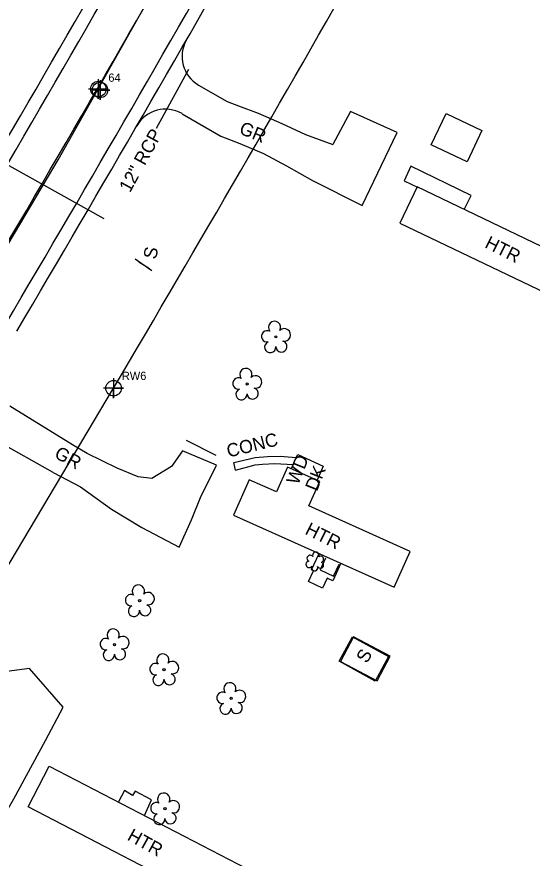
# Model space of a CAD drawing. Extents: x 1653123 to 1656194, y 596584 to 600233.
# Drawn here: x 1654045 to 1654201, y 598328.6 to 598583.3 of the extents above; entities that cross this region are included whole.
import ezdxf

# ---------------------------------------------------------------- set-up
doc = ezdxf.new("R2010")
doc.units = 0
for name, color, linetype in [('Default Symbol CELL', 7, 'Continuous'), ('Default Symbol Cogo Number', 7, 'Continuous'), ('Exist Building Text', 7, 'Continuous'), ('Exist Horizontal Alignment', 7, 'Continuous'), ('Exist Other Culture Area Outline Text', 7, 'Continuous'), ('Exist Other Culture Sign CELL', 7, 'Continuous'), ('Exist Other Culture Sign Text', 7, 'Continuous'), ('Exist Right of Way Line', 7, 'Continuous'), ('Exist Roads EOT', 7, 'Continuous'), ('Exist Roads Soil Text', 7, 'Continuous'), ('Exist Structure Minor Pipes RCP 12 Inch', 7, 'Continuous'), ('Exist Structure Minor Pipes RCP 12 Inch Text', 7, 'Continuous'), ('Exist Structure Minor Pipes RCP 18 Inch', 7, 'Continuous'), ('Exist Vegetation Tree CELL', 7, 'Continuous'), ('Old_Level_20', 7, 'Continuous'), ('Prop Conc Shoulder Berm Gutter', 7, 'Continuous'), ('Prop Easement Construction', 7, 'Continuous'), ('Prop Easement Permanent Drainage Station Offsets', 7, 'Continuous'), ('Prop ROW Station Offsets', 7, 'Continuous'), ('Prop Superelevation Label', 7, 'Continuous'), ('Scratch_Level_5', 7, 'Continuous')]:
    doc.layers.add(name, color=color, linetype=linetype)

msp = doc.modelspace()

# ---------------------------------------------------------------- linework, layer by layer
at = {"layer": 'Default Symbol CELL'}
for points in [[(1654069.68, 598564.47), (1654069.68, 598558.47), (1654069.68, 598561.47), (1654072.68, 598561.47), (1654066.68, 598561.47)], [(1654070.2, 598564.17), (1654070.2, 598558.17), (1654070.2, 598561.17), (1654073.2, 598561.17), (1654067.2, 598561.17)], [(1654074.29, 598473.91), (1654074.29, 598467.91), (1654074.29, 598470.91), (1654077.29, 598470.91), (1654071.29, 598470.91)]]:
    msp.add_lwpolyline(points, dxfattribs=at)
for centre in [(1654069.68, 598561.47), (1654070.2, 598561.17), (1654074.29, 598470.91)]:
    msp.add_circle(centre, 2.34, dxfattribs=at)
at = {"layer": 'Exist Horizontal Alignment'}
msp.add_arc((1646280.41, 603070.7), 9000, 329.451735, 330.4149, dxfattribs=at)
at = {"layer": 'Exist Other Culture Sign CELL'}
msp.add_line((1654080.82, 598510.08), (1654085.9, 598506.51), dxfattribs=at)
msp.add_lwpolyline([(1654081.92, 598509.18), (1654085.19, 598507.14)], dxfattribs=at)
at = {"layer": 'Exist Right of Way Line'}
msp.add_line((1654023, 598384.74), (1654074.29, 598470.91), dxfattribs=at)
for radius in [8950, 9050]:
    msp.add_arc((1646280.41, 603070.7), radius, 329.451735, 330.4149, dxfattribs=at)
at = {"layer": 'Exist Roads EOT'}
for radius in [8988, 9012]:
    msp.add_arc((1646280.41, 603070.7), radius, 329.451735, 330.4149, dxfattribs=at)
at = {"layer": 'Exist Structure Minor Pipes RCP 12 Inch'}
msp.add_lwpolyline([(1654087.24, 598549.61), (1654097.07, 598567.54)], dxfattribs=at)
at = {"layer": 'Exist Structure Minor Pipes RCP 18 Inch'}
msp.add_line((1654029.13, 598545.84), (1654071.38, 598522.3), dxfattribs=at)
at = {"layer": 'Exist Vegetation Tree CELL'}
for p, q in [((1654123.42, 598486.46), (1654123.42, 598486.46)), ((1654114.72, 598472.19), (1654114.72, 598472.19)), ((1654082.19, 598406.62), (1654082.19, 598406.62)), ((1654074.56, 598393.29), (1654074.56, 598393.29)), ((1654089.58, 598385.73), (1654089.58, 598385.73)), ((1654109.88, 598377.02), (1654109.88, 598377.02)), ((1654089.86, 598343.62), (1654089.86, 598343.62))]:
    msp.add_line(p, q, dxfattribs=at)
for centre in [(1654123.42, 598486.46), (1654114.72, 598472.19), (1654082.19, 598406.62), (1654074.56, 598393.29), (1654089.58, 598385.73), (1654109.88, 598377.02), (1654089.86, 598343.62)]:
    msp.add_circle(centre, 0.326, dxfattribs=at)
for centre, radius, start, end in [((1654123.03, 598489.33), 1.86, 330.1651, 219.7134), ((1654120.81, 598486.61), 1.73, 62.6636, 279.3457), ((1654125.97, 598487.05), 1.9, 257.1011, 134.1999), ((1654121.71, 598483.34), 1.69, 111.5671, 6.231), ((1654125.09, 598483.56), 1.7, 181.2822, 74.56), ((1654114.34, 598475.07), 1.86, 330.1651, 219.7134), ((1654117.27, 598472.78), 1.9, 257.1011, 134.1999), ((1654112.12, 598472.35), 1.73, 62.6636, 279.3457), ((1654113.02, 598469.07), 1.69, 111.5671, 6.231), ((1654116.4, 598469.29), 1.7, 181.2822, 74.56), ((1654081.8, 598409.49), 1.86, 330.1651, 219.7134), ((1654079.58, 598406.77), 1.73, 62.6636, 279.3457), ((1654084.74, 598407.2), 1.9, 257.1011, 134.1999), ((1654080.48, 598403.49), 1.69, 111.5671, 6.231), ((1654083.86, 598403.72), 1.7, 181.2822, 74.56), ((1654074.17, 598396.17), 1.86, 330.1651, 219.7134), ((1654077.11, 598393.88), 1.9, 257.1011, 134.1999), ((1654071.95, 598393.45), 1.73, 62.6636, 279.3457), ((1654072.85, 598390.17), 1.69, 111.5671, 6.231), ((1654076.23, 598390.4), 1.7, 181.2822, 74.56), ((1654089.2, 598388.61), 1.86, 330.1651, 219.7134), ((1654092.13, 598386.32), 1.9, 257.1011, 134.1999), ((1654086.98, 598385.89), 1.73, 62.6636, 279.3457), ((1654087.88, 598382.61), 1.69, 111.5671, 6.231), ((1654091.25, 598382.83), 1.7, 181.2822, 74.56), ((1654109.49, 598379.9), 1.86, 330.1651, 219.7134), ((1654107.27, 598377.18), 1.73, 62.6636, 279.3457), ((1654112.43, 598377.61), 1.9, 257.1011, 134.1999), ((1654108.17, 598373.9), 1.69, 111.5671, 6.231), ((1654111.55, 598374.12), 1.7, 181.2822, 74.56), ((1654089.47, 598346.5), 1.86, 330.1651, 219.7134), ((1654087.25, 598343.78), 1.73, 62.6636, 279.3457), ((1654092.4, 598344.21), 1.9, 257.1011, 134.1999), ((1654091.53, 598340.72), 1.7, 181.2822, 74.56), ((1654088.15, 598340.5), 1.69, 111.5671, 6.231)]:
    msp.add_arc(centre, radius, start, end, dxfattribs=at)
at = {"layer": 'Old_Level_20'}
msp.add_arc((1646280.41, 603070.7), 9000, 329.451735, 330.4149, dxfattribs=at)
at = {"layer": 'Prop Conc Shoulder Berm Gutter'}
for radius in [8984, 9016]:
    msp.add_arc((1646280.41, 603070.7), radius, 329.451735, 330.4149, dxfattribs=at)
at = {"layer": 'Prop Easement Construction'}
for p, q in [((1654100.03, 598562.68), (1654108.72, 598557.67)), ((1654095.03, 598554.02), (1654106.81, 598547.22)), ((1654061.81, 598453.76), (1654042.84, 598465.46)), ((1654055.98, 598445.44), (1654037.09, 598455.99))]:
    msp.add_line(p, q, dxfattribs=at)
for points in [[(1654108.72, 598557.67), (1654112.12, 598556.4), (1654118.1, 598554.14), (1654125.27, 598551.04), (1654132.43, 598547.72), (1654140.68, 598544.7)], [(1654134.51, 598533.81), (1654149.51, 598526.19), (1654160.16, 598548.34), (1654145.99, 598554.66), (1654140.68, 598544.7)], [(1654106.81, 598547.22), (1654112.5, 598544.94), (1654119.67, 598541.93), (1654126.65, 598538.24), (1654134.51, 598533.81)], [(1654055.98, 598445.44), (1654064.28, 598441.04), (1654073.67, 598434.27), (1654082.8, 598428.7), (1654094.19, 598422.76), (1654097.92, 598431.06), (1654100.58, 598437.85), (1654105.43, 598447.65), (1654095.21, 598451.99), (1654091.78, 598447.18), (1654085.83, 598443.53), (1654081.74, 598444.13), (1654075.41, 598446.7), (1654066.34, 598451.13), (1654061.81, 598453.76)], [(1654002, 598358.5), (1654006.49, 598348.61), (1654016.74, 598328.65), (1654027.24, 598313.26), (1654040.34, 598300.63), (1654054.69, 598291.88), (1654068.35, 598285.43), (1654087.8, 598279.07), (1654092.14, 598298.48), (1654076.43, 598302.81), (1654060.31, 598312.8), (1654045.42, 598322.58), (1654037.28, 598329.83), (1654036.39, 598333.41), (1654044.1, 598346.57), (1654053.67, 598364.29), (1654059.06, 598374.41), (1654048.81, 598386.03), (1654035.78, 598384.3), (1654023.46, 598382.05), (1654016.76, 598381.84), (1654011.42, 598370.7)]]:
    msp.add_lwpolyline(points, dxfattribs=at)
for centre, start, end in [((1654105.02, 598571.34), 150.1, 240.0365), ((1654090.03, 598545.37), 59.9731, 149.9096)]:
    msp.add_arc(centre, 10, start, end, dxfattribs=at)
at = {"layer": 'Prop Easement Permanent Drainage Station Offsets'}
for points in [[(1654181.31, 598539.44), (1654170.46, 598544.56), (1654174.94, 598554.05), (1654185.79, 598548.93)], [(1654160.93, 598520.88), (1654221.34, 598492.01), (1654226.57, 598502.96), (1654166.16, 598531.83)], [(1654110.56, 598432.51), (1654159.28, 598410.64), (1654164.13, 598421.45), (1654133.36, 598435.26), (1654136.69, 598442.69), (1654126.97, 598447.05), (1654123.6, 598439.53), (1654115.37, 598443.22)], [(1654146.63, 598395.64), (1654157.55, 598389.65), (1654153.49, 598382.26), (1654142.58, 598388.26)], [(1654143.01, 598388.18), (1654154.11, 598382.33), (1654158.06, 598389.84), (1654146.96, 598395.68)], [(1654054.84, 598356.52), (1654114.73, 598325.45), (1654108.32, 598313.09), (1654048.43, 598344.15)]]:
    msp.add_lwpolyline(points, close=True, dxfattribs=at)
at = {"layer": 'Prop ROW Station Offsets'}
for points in [[(1654180.44, 598525.01), (1654182.5, 598529.24), (1654164.31, 598538.14), (1654162.31, 598533.7), (1654166.5, 598531.69)], [(1654105.39, 598450.59), (1654096.38, 598455.06)], [(1654111.24, 598446.08), (1654110.74, 598448.47), (1654117.13, 598449.97), (1654120.9, 598450.29), (1654124.71, 598450.34), (1654129.56, 598449.91), (1654130.05, 598450.88), (1654137.77, 598447.33), (1654135.91, 598443.04)], [(1654111.24, 598446.08), (1654117.14, 598447.68), (1654119.33, 598447.92), (1654123.13, 598448.13), (1654128.7, 598447.86), (1654128.08, 598446.48)], [(1654143.1, 598417.91), (1654140.7, 598412.65), (1654138.97, 598413.44), (1654137.59, 598410.42), (1654133.29, 598412.38), (1654134.78, 598415.65), (1654134.26, 598415.89), (1654136.52, 598420.86)], [(1654138.48, 598419.45), (1654136.83, 598415.94), (1654140.86, 598414.01), (1654142.55, 598417.68)], [(1654083.62, 598341.59), (1654085.81, 598346.32), (1654080.84, 598348.96), (1654080.03, 598347.63), (1654077.6, 598349.11), (1654075.77, 598345.66)]]:
    msp.add_lwpolyline(points, dxfattribs=at)
at = {"layer": 'Prop Superelevation Label'}
msp.add_line((1654135.29, 598418.27), (1654135.29, 598418.27), dxfattribs=at)
for centre, radius, start, end in [((1654135.52, 598420.31), 0.99, 334.8391, 200.4717), ((1654133.81, 598419.4), 0.968, 35.8908, 245.4216), ((1654136.96, 598419.14), 0.929, 284.4567, 126.0861), ((1654133.49, 598417.57), 0.955, 95.1099, 327.9534), ((1654135.16, 598416.59), 0.984, 151.2797, 21.387), ((1654136.93, 598417.34), 0.937, 204.9913, 73.4601)]:
    msp.add_arc(centre, radius, start, end, dxfattribs=at)
at = {"layer": 'Scratch_Level_5'}
for p, q in [((1654057.57, 598540.05), (1654321.04, 599008.84)), ((1653897.29, 598271.12), (1654057.57, 598540.05))]:
    msp.add_line(p, q, dxfattribs=at)

# ---------------------------------------------------------------- texts
at = {"layer": 'Default Symbol Cogo Number'}
for s, p in [('64', (1654072.7, 598563.67)), ('RW6', (1654076.79, 598473.41))]:
    msp.add_text(s, height=2.5, dxfattribs=at).set_placement(p)
at = {"layer": 'Exist Building Text'}
for s, rotation, p in [('HTR', 333.435, (1654186.36, 598513.62)), ('HTR', 333.435, (1654131.96, 598426.9)), ('S', 60.6199, (1654151.01, 598387.4)), ('HTR', 330.9454, (1654078.15, 598334.33))]:
    msp.add_text(s, height=4, rotation=rotation, dxfattribs=at).set_placement(p)
at = {"layer": 'Exist Other Culture Area Outline Text'}
for s, rotation, p in [('CONC', 13.7723, (1654109.08, 598449.9)), ('WD', 68.1735, (1654130.16, 598441.41)), ('DK', 68.1735, (1654135.86, 598439.5))]:
    msp.add_text(s, height=4, rotation=rotation, dxfattribs=at).set_placement(p)
at = {"layer": 'Exist Other Culture Sign Text'}
msp.add_text('S', height=4, rotation=78.1009, dxfattribs=at).set_placement((1654087.14, 598509.73))
at = {"layer": 'Exist Roads Soil Text'}
for rotation, p in [(337.6317, (1654112.02, 598548.11)), (331.225, (1654056.07, 598450.06))]:
    msp.add_text('GR', height=4, rotation=rotation, dxfattribs=at).set_placement(p)
at = {"layer": 'Exist Structure Minor Pipes RCP 12 Inch Text'}
msp.add_text('12" RCP', height=4, rotation=61.2685, dxfattribs=at).set_placement((1654079.25, 598529.9))

doc.saveas('drawing.dxf')
